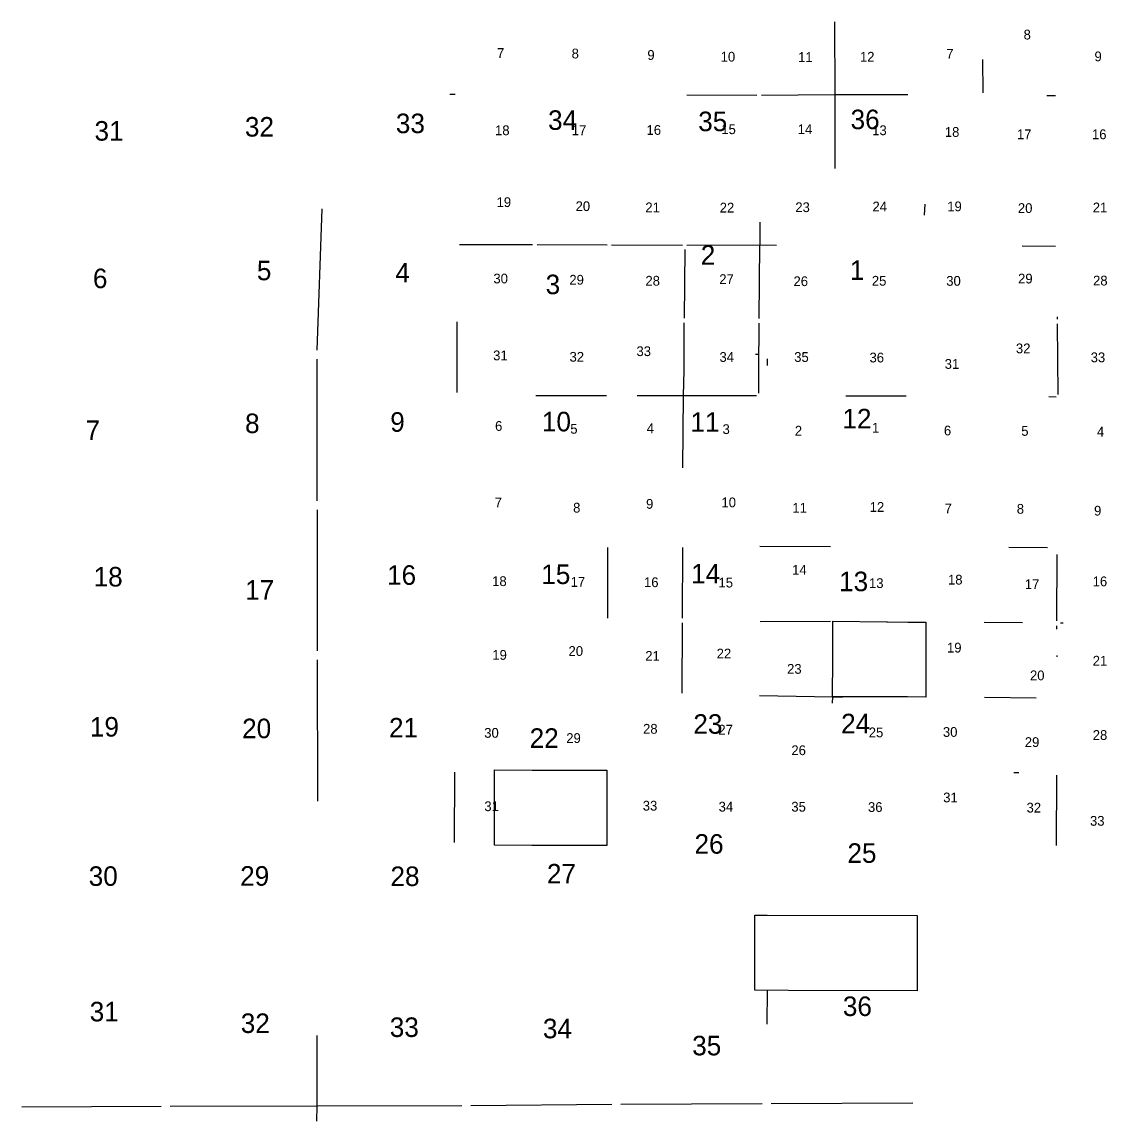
# Model space of a CAD drawing. Extents: x -2933025 to 31692252, y -2344676 to 23854604.
# Drawn here: x -2155950 to -2117830, y -2227040 to -2188443 of the extents above; entities that cross this region are included whole.
import ezdxf

# ---------------------------------------------------------------- set-up
doc = ezdxf.new("R2010")
doc.units = 0
for name, color, linetype in [('tdCoCorpBndry', 7, 'Continuous'), ('tdCoSectLinePart', 7, 'Continuous'), ('tdCoSectNmbr', 7, 'Continuous')]:
    doc.layers.add(name, color=color, linetype=linetype)

msp = doc.modelspace()

# ---------------------------------------------------------------- linework, layer by layer
at = {"layer": 'tdCoCorpBndry'}
for points in [[(-2127462, -2209483), (-2125572, -2209504), (-2125548, -2209505), (-2125542, -2209505), (-2125537, -2209505), (-2124834, -2209517), (-2124190, -2209521), (-2124191, -2212150), (-2124838, -2212147), (-2126942, -2212144), (-2127479, -2212137), (-2127467, -2210795)], [(-2139345, -2214711), (-2138030, -2214717), (-2135399, -2214723), (-2135403, -2217364), (-2137663, -2217360), (-2137849, -2217360), (-2138035, -2217360), (-2139355, -2217351)], [(-2130202, -2219808), (-2129771, -2219810), (-2124498, -2219826), (-2124500, -2221125), (-2124496, -2222464), (-2129021, -2222452), (-2130200, -2222449), (-2130199, -2221152)]]:
    msp.add_lwpolyline(points, close=True, dxfattribs=at)
at = {"layer": 'tdCoSectLinePart'}
for points in [[(-2127404, -2188443), (-2127393, -2190994)], [(-2122186, -2190931), (-2122189, -2189765)], [(-2140920, -2190981), (-2140735, -2190981)], [(-2132589, -2191000), (-2130131, -2191011)], [(-2129973, -2191011), (-2127393, -2190994)], [(-2127393, -2190994), (-2124824, -2190987)], [(-2127393, -2190994), (-2127387, -2193583)], [(-2119945, -2191028), (-2119639, -2191030)], [(-2124236, -2194846), (-2124256, -2195228)], [(-2145579, -2199969), (-2145406, -2195008)], [(-2130025, -2195473), (-2130029, -2196274)], [(-2140581, -2196261), (-2138013, -2196257)], [(-2137855, -2196257), (-2135392, -2196264)], [(-2135234, -2196265), (-2132745, -2196285)], [(-2132667, -2196438), (-2132683, -2198848)], [(-2132587, -2196285), (-2130029, -2196274)], [(-2130051, -2198859), (-2130029, -2196274)], [(-2130029, -2196274), (-2129444, -2196282)], [(-2120813, -2196307), (-2119638, -2196314)], [(-2119570, -2198881), (-2119570, -2198799)], [(-2140665, -2201458), (-2140664, -2200703), (-2140663, -2200661), (-2140658, -2198979)], [(-2132706, -2201565), (-2132682, -2200687), (-2132682, -2200651), (-2132682, -2200598), (-2132684, -2199007)], [(-2130068, -2201484), (-2130058, -2200702), (-2130060, -2200646), (-2130052, -2199017)], [(-2119551, -2201528), (-2119570, -2199039)], [(-2145581, -2205254), (-2145584, -2200286)], [(-2130175, -2200105), (-2130056, -2200103)], [(-2129765, -2200268), (-2129766, -2200505)], [(-2137902, -2201560), (-2135420, -2201564)], [(-2134332, -2201565), (-2132706, -2201565)], [(-2132729, -2204105), (-2132706, -2201565)], [(-2132706, -2201565), (-2130142, -2201558)], [(-2127009, -2201576), (-2124882, -2201574)], [(-2119871, -2201601), (-2119620, -2201602)], [(-2145581, -2205570), (-2145581, -2210525)], [(-2135369, -2209378), (-2135363, -2206899)], [(-2132744, -2209381), (-2132732, -2206904)], [(-2130022, -2206855), (-2127545, -2206860)], [(-2121277, -2206892), (-2119925, -2206903)], [(-2119589, -2209477), (-2119579, -2207142)], [(-2132753, -2212013), (-2132745, -2209539)], [(-2130017, -2209495), (-2127543, -2209484)], [(-2122144, -2209523), (-2120798, -2209533)], [(-2119589, -2209763), (-2119589, -2209649)], [(-2119468, -2209541), (-2119373, -2209542)], [(-2119587, -2210737), (-2119587, -2210689)], [(-2145581, -2210841), (-2145565, -2215804)], [(-2130035, -2212095), (-2127468, -2212143)], [(-2127469, -2212365), (-2127468, -2212143)], [(-2127468, -2212143), (-2127468, -2212137)], [(-2127468, -2212143), (-2127114, -2212143)], [(-2122138, -2212158), (-2120323, -2212174)], [(-2140752, -2214786), (-2140769, -2217261)], [(-2121100, -2214797), (-2120929, -2214798)], [(-2119600, -2217363), (-2119596, -2214888)], [(-2129774, -2222450), (-2129777, -2223633)], [(-2145580, -2226511), (-2145578, -2224042)], [(-2155950, -2226544), (-2151058, -2226519)], [(-2150741, -2226517), (-2145580, -2226511)], [(-2145590, -2227040), (-2145580, -2226511)], [(-2145580, -2226511), (-2140496, -2226498)], [(-2140179, -2226496), (-2135224, -2226444)], [(-2134909, -2226442), (-2129943, -2226428)], [(-2129627, -2226427), (-2124651, -2226402)]]:
    msp.add_lwpolyline(points, dxfattribs=at)

# ---------------------------------------------------------------- texts
at = {"layer": 'tdCoSectNmbr'}
for s, height, rotation, p in [('8', 343, 0.0063, (-2120761, -2189057)), ('7', 343, 0.0009, (-2139261, -2189704)), ('8', 343, 0.0017, (-2136639, -2189722)), ('9', 343, 0.0024, (-2133979, -2189773)), ('10', 343.2, 0.0032, (-2131404, -2189834)), ('11', 343.2, 0.004, (-2128683, -2189846)), ('12', 343.2, 0.0046, (-2126511, -2189837)), ('7', 343, 0.0055, (-2123478, -2189734)), ('9', 343, 0.007, (-2118271, -2189823)), ('36', 686.4, 0.0197, (-2126839, -2192208)), ('32', 686.4, 0.0166, (-2148117, -2192468)), ('33', 686.4, 0.0174, (-2142815, -2192347)), ('34', 686.4, 0.0182, (-2137467, -2192232)), ('35', 686.4, 0.0189, (-2132193, -2192277)), ('31', 686.4, 0.0158, (-2153401, -2192610)), ('18', 343.2, 0.0008, (-2139330, -2192418)), ('17', 343.2, 0.0016, (-2136633, -2192418)), ('16', 343.2, 0.0024, (-2134008, -2192407)), ('15', 343.2, 0.0032, (-2131381, -2192381)), ('14', 343.2, 0.0039, (-2128697, -2192382)), ('13', 343.2, 0.0047, (-2126081, -2192418)), ('18', 343.2, 0.0054, (-2123528, -2192477)), ('17', 343.2, 0.0062, (-2120996, -2192560)), ('16', 343.2, 0.007, (-2118359, -2192560)), ('19', 343.2, 0.0009, (-2139277, -2194942)), ('20', 343.2, 0.0016, (-2136501, -2195084)), ('21', 343.2, 0.0024, (-2134050, -2195126)), ('22', 343.2, 0.0031, (-2131437, -2195134)), ('23', 343.2, 0.0039, (-2128782, -2195120)), ('24', 343.2, 0.0047, (-2126071, -2195097)), ('19', 343.2, 0.0055, (-2123444, -2195091)), ('20', 343.2, 0.0062, (-2120962, -2195151)), ('21', 343.2, 0.0069, (-2118331, -2195129)), ('2', 686, 0.0188, (-2132104, -2196969)), ('5', 686, 0.0166, (-2147697, -2197513)), ('4', 686, 0.0173, (-2142832, -2197591)), ('1', 686, 0.0196, (-2126864, -2197499)), ('6', 686, 0.0157, (-2153457, -2197790)), ('30', 343.2, 0.0008, (-2139388, -2197624)), ('3', 686, 0.018, (-2137552, -2198002)), ('27', 343.2, 0.0032, (-2131453, -2197645)), ('29', 343.2, 0.0062, (-2120955, -2197625)), ('29', 343.2, 0.0016, (-2136719, -2197668)), ('28', 343.2, 0.0024, (-2134047, -2197703)), ('26', 343.2, 0.0039, (-2128845, -2197719)), ('25', 343.2, 0.0047, (-2126092, -2197704)), ('30', 343.2, 0.0054, (-2123478, -2197707)), ('28', 343.2, 0.0069, (-2118321, -2197696)), ('31', 343.2, 0.0008, (-2139397, -2200324)), ('33', 343.2, 0.0024, (-2134362, -2200176)), ('32', 343.2, 0.0062, (-2121031, -2200078)), ('32', 343.2, 0.0016, (-2136713, -2200374)), ('34', 343.2, 0.0031, (-2131446, -2200380)), ('35', 343.2, 0.0039, (-2128820, -2200381)), ('36', 343.2, 0.0047, (-2126175, -2200399)), ('31', 343.2, 0.0054, (-2123534, -2200624)), ('33', 343.2, 0.0069, (-2118404, -2200392)), ('8', 686, 0.0164, (-2148112, -2202881)), ('9', 686, 0.0172, (-2143012, -2202833)), ('10', 686.4, 0.0179, (-2137684, -2202820)), ('11', 686.4, 0.0187, (-2132465, -2202836)), ('12', 686.4, 0.0195, (-2127126, -2202716)), ('7', 686, 0.0156, (-2153715, -2203122)), ('6', 343, 0.0008, (-2139329, -2202802)), ('5', 343, 0.0016, (-2136686, -2202902)), ('4', 343, 0.0023, (-2134001, -2202884)), ('3', 343, 0.0032, (-2131338, -2202914)), ('2', 343, 0.0039, (-2128798, -2202970)), ('1', 343, 0.0046, (-2126088, -2202864)), ('6', 343, 0.0054, (-2123560, -2202962)), ('5', 343, 0.0062, (-2120843, -2202976)), ('4', 343, 0.0069, (-2118186, -2203003)), ('7', 343, 0.0008, (-2139339, -2205487)), ('8', 343, 0.0016, (-2136587, -2205672)), ('9', 343, 0.0023, (-2134025, -2205538)), ('10', 343.2, 0.0031, (-2131375, -2205485)), ('11', 343.2, 0.0038, (-2128886, -2205678)), ('12', 343.2, 0.0046, (-2126168, -2205647)), ('7', 343, 0.0054, (-2123535, -2205698)), ('8', 343, 0.0061, (-2121001, -2205712)), ('9', 343, 0.0069, (-2118286, -2205777)), ('18', 686.4, 0.0155, (-2153432, -2208268)), ('16', 686.4, 0.0171, (-2143124, -2208209)), ('15', 686.4, 0.0178, (-2137706, -2208182)), ('14', 686.4, 0.0186, (-2132442, -2208162)), ('14', 343.2, 0.0038, (-2128894, -2207854)), ('17', 686.4, 0.0163, (-2148107, -2208730)), ('18', 343.2, 0.0007, (-2139431, -2208252)), ('17', 343.2, 0.0015, (-2136676, -2208280)), ('16', 343.2, 0.0022, (-2134097, -2208291)), ('15', 343.2, 0.003, (-2131480, -2208303)), ('13', 686.4, 0.0193, (-2127243, -2208433)), ('13', 343.2, 0.0046, (-2126192, -2208322)), ('18', 343.2, 0.0053, (-2123417, -2208199)), ('17', 343.2, 0.0062, (-2120717, -2208356)), ('16', 343.2, 0.0068, (-2118334, -2208259)), ('20', 343.2, 0.0015, (-2136748, -2210706)), ('19', 343.2, 0.0053, (-2123453, -2210586)), ('19', 343.2, 0.0007, (-2139426, -2210842)), ('21', 343.2, 0.0023, (-2134053, -2210876)), ('22', 343.2, 0.003, (-2131544, -2210794)), ('21', 343.2, 0.0068, (-2118333, -2211047)), ('23', 343.2, 0.0038, (-2129070, -2211333)), ('20', 343.2, 0.0062, (-2120537, -2211561)), ('23', 686.4, 0.0185, (-2132364, -2213440)), ('24', 686.4, 0.0193, (-2127171, -2213424)), ('19', 686.4, 0.0155, (-2153563, -2213539)), ('20', 686.4, 0.0162, (-2148215, -2213596)), ('21', 686.4, 0.017, (-2143056, -2213569)), ('28', 343.2, 0.0022, (-2134130, -2213438)), ('27', 343.2, 0.003, (-2131485, -2213469)), ('30', 343.2, 0.0007, (-2139710, -2213580)), ('22', 686.4, 0.0178, (-2138114, -2213935)), ('29', 343.2, 0.0015, (-2136828, -2213763)), ('25', 343.2, 0.0045, (-2126201, -2213563)), ('30', 343.2, 0.0053, (-2123596, -2213548)), ('28', 343.2, 0.0068, (-2118331, -2213656)), ('26', 343.2, 0.0037, (-2128919, -2214191)), ('29', 343.2, 0.0061, (-2120719, -2213905)), ('31', 343.2, 0.0006, (-2139707, -2216156)), ('33', 343.2, 0.0022, (-2134141, -2216138)), ('34', 343.2, 0.003, (-2131475, -2216173)), ('35', 343.2, 0.0037, (-2128920, -2216174)), ('31', 343.2, 0.0053, (-2123586, -2215849)), ('36', 343.2, 0.0045, (-2126228, -2216186)), ('32', 343.2, 0.0061, (-2120657, -2216205)), ('33', 343.2, 0.0068, (-2118429, -2216670)), ('26', 686.4, 0.0184, (-2132322, -2217651)), ('25', 686.4, 0.0192, (-2126950, -2217973)), ('30', 686.4, 0.0153, (-2153605, -2218782)), ('29', 686.4, 0.0161, (-2148284, -2218776)), ('28', 686.4, 0.0169, (-2143004, -2218787)), ('27', 686.4, 0.0177, (-2137507, -2218698)), ('36', 686.4, 0.0191, (-2127111, -2223352)), ('31', 686.4, 0.0153, (-2153570, -2223540)), ('32', 686.4, 0.0161, (-2148263, -2223948)), ('33', 686.4, 0.0168, (-2143028, -2224088)), ('34', 686.4, 0.0176, (-2137649, -2224134)), ('35', 686.4, 0.0183, (-2132404, -2224734))]:
    msp.add_text(s, height=height, rotation=rotation, dxfattribs=at).set_placement(p)

doc.saveas('drawing.dxf')
